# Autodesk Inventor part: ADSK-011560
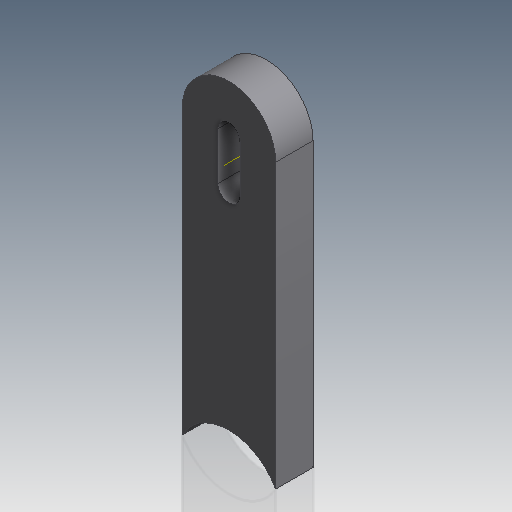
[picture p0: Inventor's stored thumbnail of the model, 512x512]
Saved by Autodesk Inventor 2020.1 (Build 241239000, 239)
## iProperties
Created: 2000-02
Part Number: ADSK-011560
Material: Pearson HRS
Document SubType Name: Modeling
Designer: sspink
Density: 7.83 g/cm^3
Appearance: Métal - Acier
Mass: 1191.22 g
Surface Area: 258.209 cm^2
Volume: 152.136 cm^3
Control State: 0
Checked Out: False
Master: False
Shininess: 0.0
Length Units: 11269
Angle Units: 11279
Time Units: 11290
Mass Units: 11283
Length Display Precision: 3
Angle Display Precision: 2
Compacted: True
Dimensions: 176,3x20x50 mm
Mass: 1,191 kg
VLT_Material: Pearson HRS
Density: 0.0
Volumn: 0.0
Area: 0.0
PropertySet Name: Model Information
Author: sspink
Revision Number: -
Title: ADSK-011560
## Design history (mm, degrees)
node "Solide1"
  node "Extrusion1" dims "d3" = 20, "d4" = 0
  node "Extrusion2" dims "d8" = 19.05, "d9" = 0
sketch "Sketch1"
  geometry: L1 (0, 0)-(0, 165); L2 (-25, 13.684)-(-25, 165); L3 (25, 13.684)-(25, 165); A1 r 28.5 centre (0, 0) between (-25, 13.684) and (25, 13.684); A2 r 25 centre (0, 165) between (-25, 165) and (25, 165); 1 further point
  constraints: 6 end point, 4 point on circle, 2 centre point, 2 coincident, 2 parallel, 2 tangent, 1 vertical
  dimensions: "d0" = 57 diameter of A1; "d1" = 165 distance of L1.start L1.end; "d2" = 50 diameter of A2
sketch "Sketch2"
  geometry: L1 (-5.953, 165)-(5.953, 165); L2 (5.953, 165)-(5.953, 139.6); L3 (5.953, 139.6)-(-5.953, 139.6); L4 (-5.953, 139.6)-(-5.953, 165); L5 (25, 13.684)-(25, 165) reference; A1 r 5.953 centre (0, 165) between (5.953, 165) and (-5.953, 165); A2 r 5.953 centre (0, 139.6) between (-5.953, 139.6) and (5.953, 139.6); A3 r 28.5 centre (0, 0) between (25, 13.684) and (-25, 13.684) reference; 2 further points; 1 other entity
  constraints: 8 end point, 4 point on circle, 2 centre point, 2 parallel, 2 tangent, 1 coincident, 1 horizontal, 1 perpendicular, 2 other
  dimensions: "d6" = 5.95312 radius of A1; "d7" = 25.4 distance of L1.end L2.end
workpoint "Arbeitspunkt1"
workaxis "Arbeitsachse3"
node "Corps solides"
node "Corps surfaciques"
